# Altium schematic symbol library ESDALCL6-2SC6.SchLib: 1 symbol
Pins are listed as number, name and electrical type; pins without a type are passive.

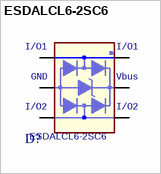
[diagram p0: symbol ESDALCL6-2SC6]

## ESDALCL6-2SC6
designator D?
footprint ST_SOT23-6L
pins: 1 I/O1, 2 GND, 3 I/O2, 4 I/O2+, 5 Vbus, 6 I/O1+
